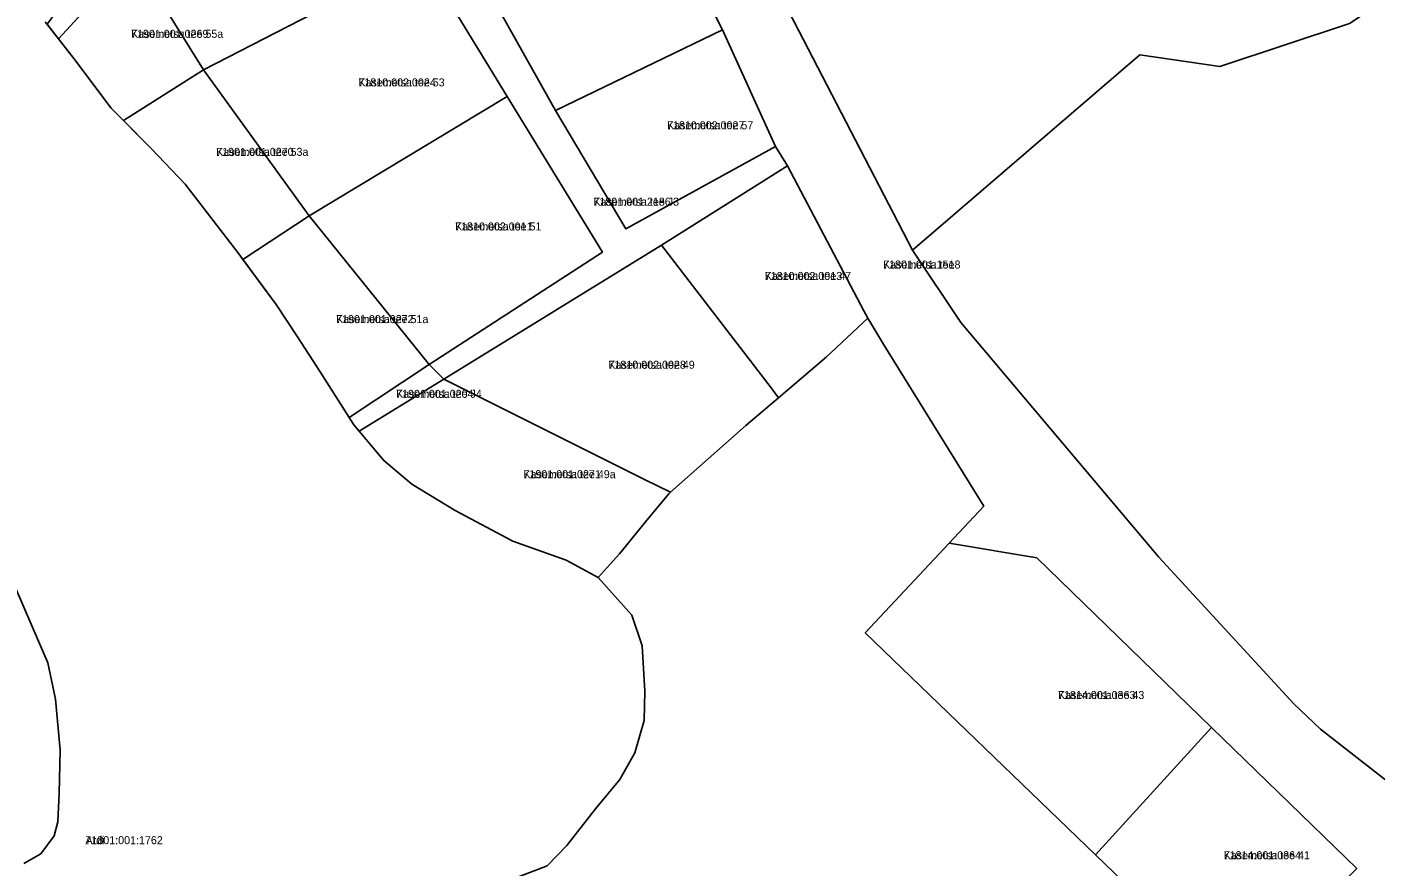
# Model space of a CAD drawing. Extents: x 529768 to 552006, y 6562269 to 6580975.
# Drawn here: x 537876.3 to 538128.9, y 6567066.6 to 6567223.9 of the extents above; entities that cross this region are included whole.
import ezdxf

# ---------------------------------------------------------------- set-up
doc = ezdxf.new("R2010")
doc.units = 0
for name, color, linetype in [('L_AADRESS', 7, 'Continuous'), ('PIIR', 7, 'Continuous'), ('TUNNUS', 7, 'Continuous')]:
    doc.layers.add(name, color=color, linetype=linetype)

msp = doc.modelspace()

# ---------------------------------------------------------------- linework, layer by layer
at = {"layer": 'PIIR'}
for points in [[(538205.94, 6567024.11), (538118.69, 6567092.24), (538113.69, 6567097), (538088.38, 6567124.5), (538051.25, 6567168.5), (538042.23, 6567182.07), (538084.84, 6567218.64), (538099.8, 6567216.46), (538124.1, 6567224.55), (538143.06, 6567237.11), (538150.95, 6567238.17), (538239.65, 6567344.96), (538263.29, 6567373.4), (538289.34, 6567404.76), (538332.86, 6567456.22), (538371.5, 6567487.1), (538375.89, 6567490.6), (538416.41, 6567523), (538417.97, 6567521.43)], [(537867.28, 6567509.8), (537885.27, 6567473.37), (537897.72, 6567452.1), (537931.9, 6567393.33), (537941.85, 6567375.7), (537952.13, 6567357.49), (537960.9, 6567341.94), (537968.08, 6567338.13), (537969.71, 6567332.41), (537967.19, 6567328.02), (537968.16, 6567326.16), (538001.41, 6567260.89), (538017.38, 6567228.01), (538018.21, 6567228.37), (538042.23, 6567182.07), (538051.25, 6567168.5), (538088.38, 6567124.5), (538113.69, 6567097), (538118.69, 6567092.24), (538205.94, 6567024.11)], [(538125.45, 6567066.11), (538098.26, 6567092.53), (538065.49, 6567124.36), (538049.09, 6567127.1), (538055.56, 6567134.02), (538036.83, 6567164.31), (538033.86, 6567169.28), (538033.13, 6567170.66), (538018.77, 6567197.83), (538016.54, 6567201.45), (538006.59, 6567223.36), (537995.66, 6567244.72)], [(537879.73, 6567224.88), (537885.05, 6567217.99), (537892.09, 6567208.67), (537899.55, 6567201.08), (537905.96, 6567194.41), (537916, 6567181.33), (537922.99, 6567171.88), (537926.98, 6567165.79), (537931.22, 6567159.24), (537937.52, 6567149.31), (537943.13, 6567142.62), (537948.38, 6567138.2), (537956.5, 6567133.23), (537967.36, 6567127.5), (537977.33, 6567123.92), (537983.33, 6567120.7), (537989.63, 6567113.59), (537991.56, 6567107.85), (537992.09, 6567099.35), (537991.96, 6567093.87), (537990.18, 6567087.78), (537987.36, 6567082.77), (537982.81, 6567077.31), (537977.43, 6567070.43), (537973.79, 6567066.64), (537968.4, 6567064.52)], [(537968.4, 6567064.52), (537973.79, 6567066.64), (537977.43, 6567070.43), (537982.81, 6567077.31), (537987.36, 6567082.77), (537990.18, 6567087.78), (537991.96, 6567093.87), (537992.09, 6567099.35), (537991.56, 6567107.85), (537989.63, 6567113.59), (537983.33, 6567120.7), (537985.54, 6567123.15), (537987.31, 6567125.11), (537992.77, 6567131.77), (537996.54, 6567136.37), (537996.87, 6567136.66), (538011.02, 6567149.2), (538017.13, 6567154.38), (538026.06, 6567161.97), (538033.86, 6567169.28), (538036.83, 6567164.31), (538055.56, 6567134.02), (538049.09, 6567127.1), (538033.38, 6567110.28), (538076.52, 6567068.68), (538102.95, 6567043.17)], [(537875.68, 6567067.03), (537878.87, 6567068.88), (537881.39, 6567072.24), (537882.06, 6567074.86), (537882.31, 6567080.23), (537882.53, 6567088.31), (537881.64, 6567097.85), (537880.18, 6567104.69), (537861.6, 6567147.72)], [(537861.6, 6567147.72), (537880.18, 6567104.69), (537881.64, 6567097.85), (537882.53, 6567088.31), (537882.31, 6567080.23), (537882.06, 6567074.86), (537881.39, 6567072.24), (537878.87, 6567068.88), (537875.68, 6567067.03)]]:
    msp.add_lwpolyline(points, dxfattribs=at)
for points in [[(538141.33, 6567258.82), (538143.06, 6567237.11), (538124.1, 6567224.55), (538099.8, 6567216.46), (538084.84, 6567218.64), (538042.23, 6567182.07), (538018.21, 6567228.37), (538138.42, 6567282.45)], [(537896.28, 6567236.98), (537932.61, 6567264.46), (537946.06, 6567243.79), (537950.33, 6567236.99), (537909.37, 6567215.88)], [(537946.06, 6567243.79), (537953.37, 6567247.7), (537963.84, 6567228.75), (537975.31, 6567208.2), (537988.5, 6567186.06), (538016.54, 6567201.45), (538018.77, 6567197.83), (537995.21, 6567182.96), (537954.39, 6567157.88), (537951.68, 6567160.61), (537984.12, 6567181.7), (537966.3, 6567210.88), (537950.33, 6567236.99)], [(537963.84, 6567228.75), (537995.66, 6567244.72), (538006.59, 6567223.36), (537975.31, 6567208.2)], [(537880.09, 6567224.41), (537893.52, 6567242.87), (537896.28, 6567236.98), (537882.2, 6567221.68)], [(537882.2, 6567221.68), (537896.28, 6567236.98), (537909.37, 6567215.88), (537894.35, 6567206.37), (537892.09, 6567208.67), (537885.05, 6567217.99)], [(537909.37, 6567215.88), (537950.33, 6567236.99), (537966.3, 6567210.88), (537929.15, 6567188.51)], [(538006.59, 6567223.36), (538016.54, 6567201.45), (537988.5, 6567186.06), (537975.31, 6567208.2)], [(537899.55, 6567201.08), (537894.35, 6567206.37), (537909.37, 6567215.88), (537929.15, 6567188.51), (537916.76, 6567180.3), (537916, 6567181.33), (537905.96, 6567194.41)], [(537966.3, 6567210.88), (537984.12, 6567181.7), (537951.68, 6567160.61), (537929.15, 6567188.51)], [(538015.73, 6567156.21), (537995.21, 6567182.96), (538018.77, 6567197.83), (538033.13, 6567170.66), (538033.86, 6567169.28), (538026.06, 6567161.97), (538017.13, 6567154.38)], [(537916.76, 6567180.3), (537929.15, 6567188.51), (537951.68, 6567160.61), (537936.66, 6567150.66), (537931.22, 6567159.24), (537926.98, 6567165.79), (537922.99, 6567171.88)], [(537995.21, 6567182.96), (538015.73, 6567156.21), (538017.13, 6567154.38), (538011.02, 6567149.2), (537996.87, 6567136.66), (537991.99, 6567139.07), (537954.39, 6567157.88)], [(537937.52, 6567149.31), (537936.66, 6567150.66), (537951.68, 6567160.61), (537954.39, 6567157.88), (537938.53, 6567148.11)], [(537983.33, 6567120.7), (537977.33, 6567123.92), (537967.36, 6567127.5), (537956.5, 6567133.23), (537948.38, 6567138.2), (537943.13, 6567142.62), (537938.53, 6567148.11), (537954.39, 6567157.88), (537991.99, 6567139.07), (537996.87, 6567136.66), (537996.54, 6567136.37), (537992.77, 6567131.77), (537987.31, 6567125.11), (537985.54, 6567123.15)], [(538033.38, 6567110.28), (538049.09, 6567127.1), (538065.49, 6567124.36), (538098.26, 6567092.53), (538076.52, 6567068.68)], [(538076.52, 6567068.68), (538098.26, 6567092.53), (538125.45, 6567066.11), (538102.95, 6567043.17)]]:
    msp.add_lwpolyline(points, close=True, dxfattribs=at)

# ---------------------------------------------------------------- texts
at = {"layer": 'L_AADRESS'}
for s, p in [('Kasemetsa tee 55a', (537895.79, 6567221.86)), ('Kasemetsa tee 53', (537938.39, 6567212.75)), ('Kasemetsa tee 57', (537996.22, 6567204.71)), ('Kasemetsa tee 53a', (537911.75, 6567199.73)), ('Kasemetsa tee J3', (537982.42, 6567190.38)), ('Kasemetsa tee 51', (537956.52, 6567185.74)), ('Kasemetsa tee', (538036.71, 6567178.6)), ('Kasemetsa tee 47', (538014.54, 6567176.46)), ('Kasemetsa tee 51a', (537934.22, 6567168.37)), ('Kasemetsa tee 49', (537985.25, 6567159.81)), ('Kasemetsa tee J4', (537945.46, 6567154.36)), ('Kasemetsa tee 49a', (537969.32, 6567139.29)), ('Kasemetsa tee 43', (538069.49, 6567097.89)), ('Ardi', (537887.24, 6567070.67)), ('Kasemetsa tee 41', (538100.52, 6567067.85))]:
    msp.add_text(s, height=1.5, dxfattribs=at).set_placement(p)
at = {"layer": 'TUNNUS'}
for s, p in [('71901:001:0269', (537895.79, 6567221.86)), ('71810:002:0024', (537938.39, 6567212.75)), ('71810:002:0027', (537996.22, 6567204.71)), ('71901:001:0270', (537911.75, 6567199.73)), ('71801:001:2186', (537982.42, 6567190.38)), ('71810:002:0011', (537956.52, 6567185.74)), ('71801:001:1518', (538036.71, 6567178.6)), ('71810:002:0013', (538014.54, 6567176.46)), ('71901:001:0272', (537934.22, 6567168.37)), ('71810:002:0028', (537985.25, 6567159.81)), ('71901:001:0204', (537945.46, 6567154.36)), ('71901:001:0271', (537969.32, 6567139.29)), ('71814:001:0363', (538069.49, 6567097.89)), ('71801:001:1762', (537887.24, 6567070.67)), ('71814:001:0364', (538100.52, 6567067.85))]:
    msp.add_text(s, height=1.5, dxfattribs=at).set_placement(p)

doc.saveas('drawing.dxf')
